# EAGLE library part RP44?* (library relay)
Power PCB Relay RP II/2 Schrack 2 pole 8 A Source: http://www.schrack.com/.. 5844.pdf
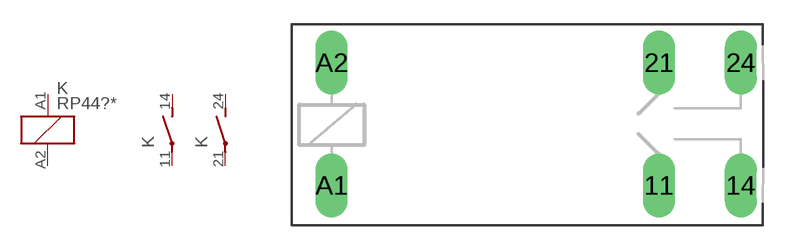
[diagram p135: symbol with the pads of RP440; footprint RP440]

Designator prefix K; gates 1=K 2=S 3=S

## RP440005 (OC_FARNELL: unknown; OC_NEWARK: unknown), RP440006 (OC_FARNELL: unknown; OC_NEWARK: unknown), RP440012 (MF: TYCO ELECTRONICS; MPN: RP440012; OC_FARNELL: unknown; OC_NEWARK: 07H9451), RP440024 (MPN: RP440024; OC_FARNELL: unknown; OC_NEWARK: 48M7816), RP440048 (OC_FARNELL: unknown; OC_NEWARK: unknown), RP440060 (OC_FARNELL: unknown; OC_NEWARK: unknown), RP440110 (OC_FARNELL: unknown; OC_NEWARK: unknown), RP441005 (OC_FARNELL: unknown; OC_NEWARK: unknown), RP441006 (OC_FARNELL: unknown; OC_NEWARK: unknown), RP441012 (MF: TYCO ELECTRONICS; MPN: RP441012; OC_FARNELL: unknown; OC_NEWARK: 09H1465), RP441024 (MPN: RP441024; OC_FARNELL: unknown; OC_NEWARK: 48M7817), RP441048 (OC_FARNELL: unknown; OC_NEWARK: unknown), RP441060 (OC_FARNELL: unknown; OC_NEWARK: unknown), RP441110 (OC_FARNELL: unknown; OC_NEWARK: unknown)  [RP440]
11  2:P  pas
14  2:S  pas
21  3:P  pas
24  3:S  pas
A1  1:1  pas
A2  1:2  pas

## Footprint RP440 (pad centres in mm)
Power PCB Relay RP II/2 SCHRACK 2 pole 8 A Source: http://www.schrack.com/.. 5844.pdf
drill 1.321 long: 11 16.51,-3.81; 14 21.59,-3.81; 21 16.51,3.81; 24 21.59,3.81; A1 -3.81,-3.81; A2 -3.81,3.81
